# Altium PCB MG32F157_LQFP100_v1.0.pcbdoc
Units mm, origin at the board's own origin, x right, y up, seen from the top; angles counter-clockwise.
Board outline 95.9 x 106.58 mm, 2 copper layers (Top Layer, Bottom Layer); 65 components, 113 nets, 356 pads, 273 vias.
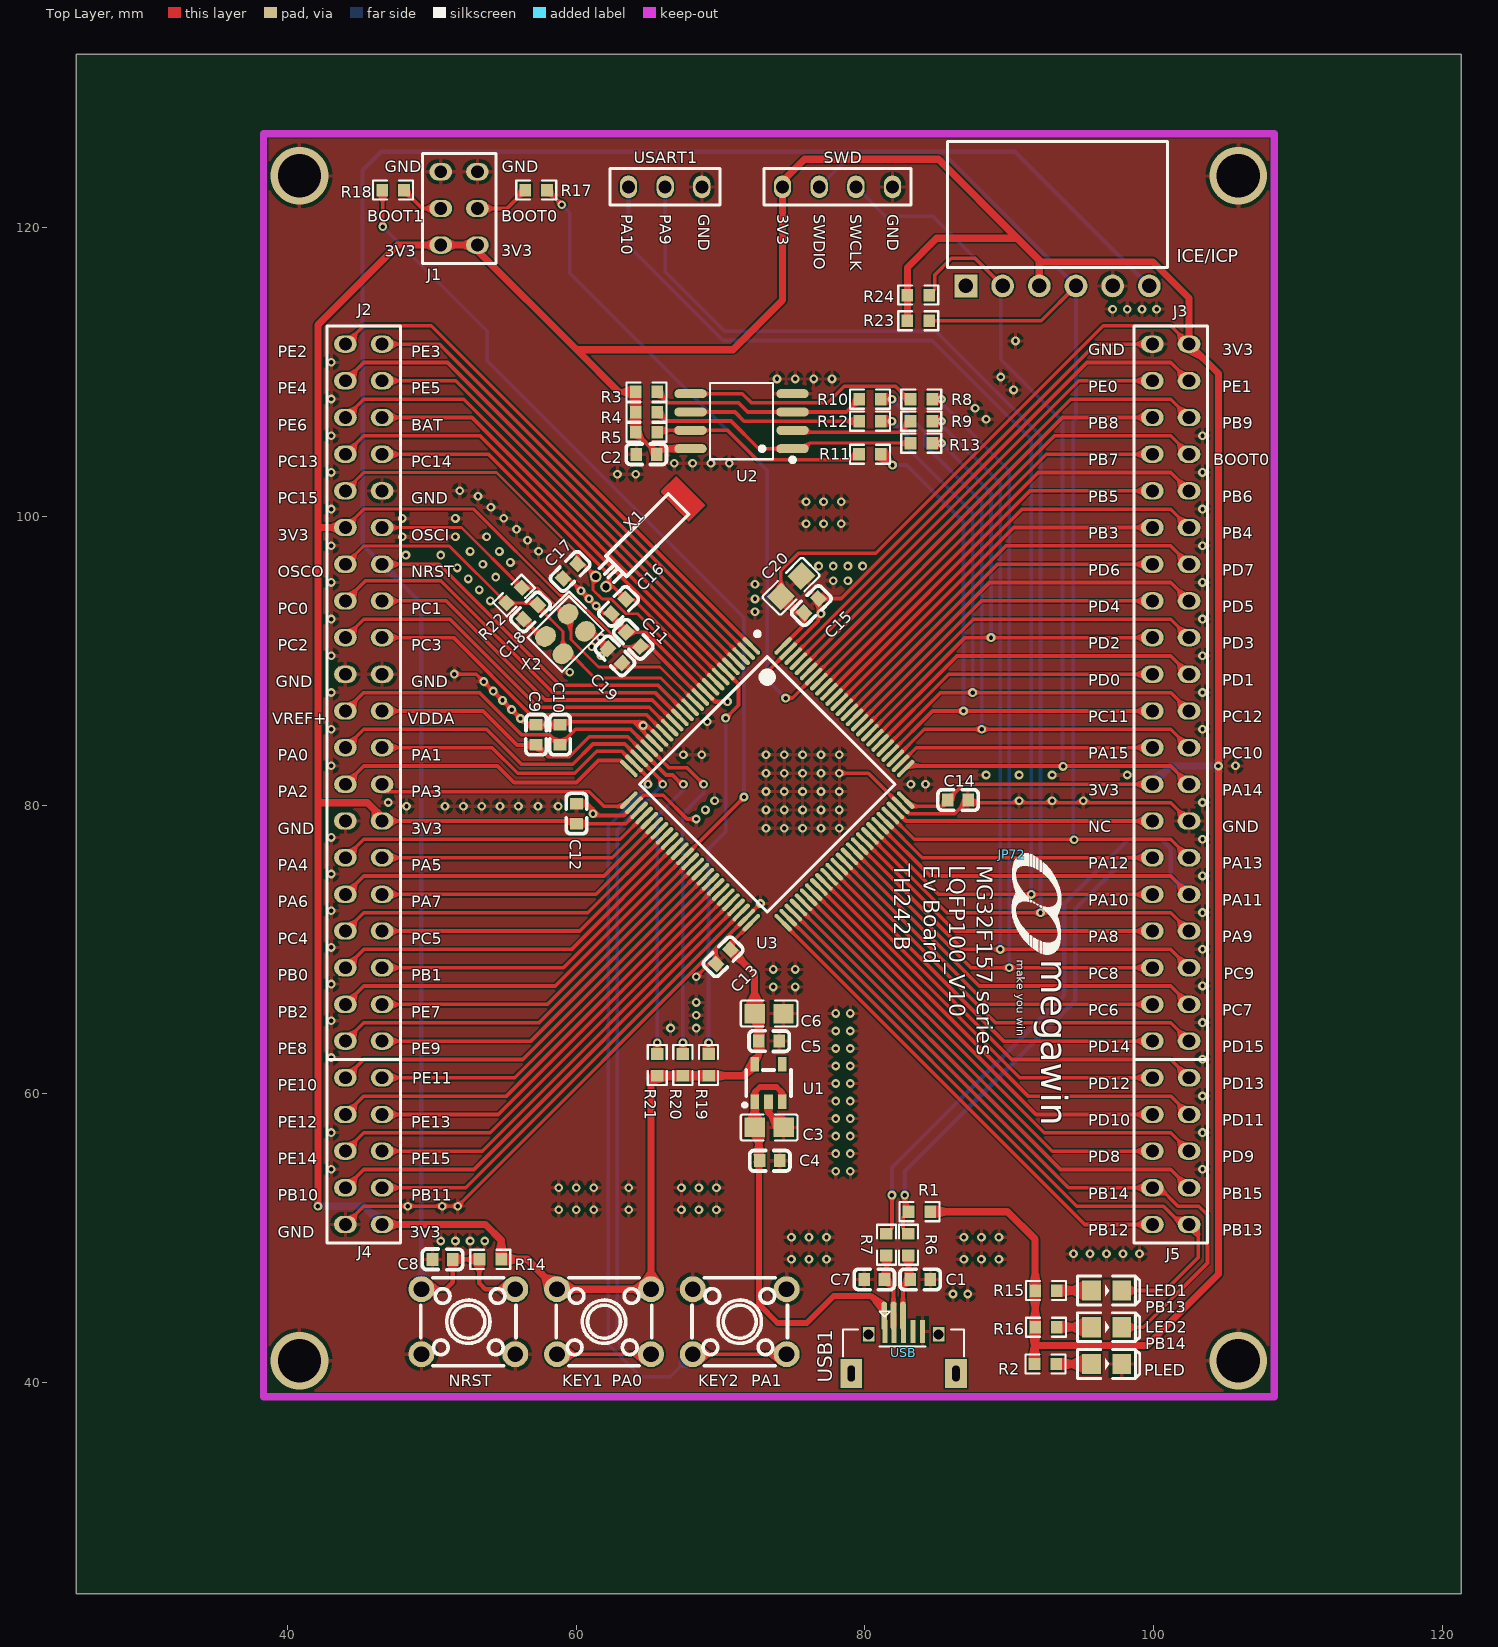
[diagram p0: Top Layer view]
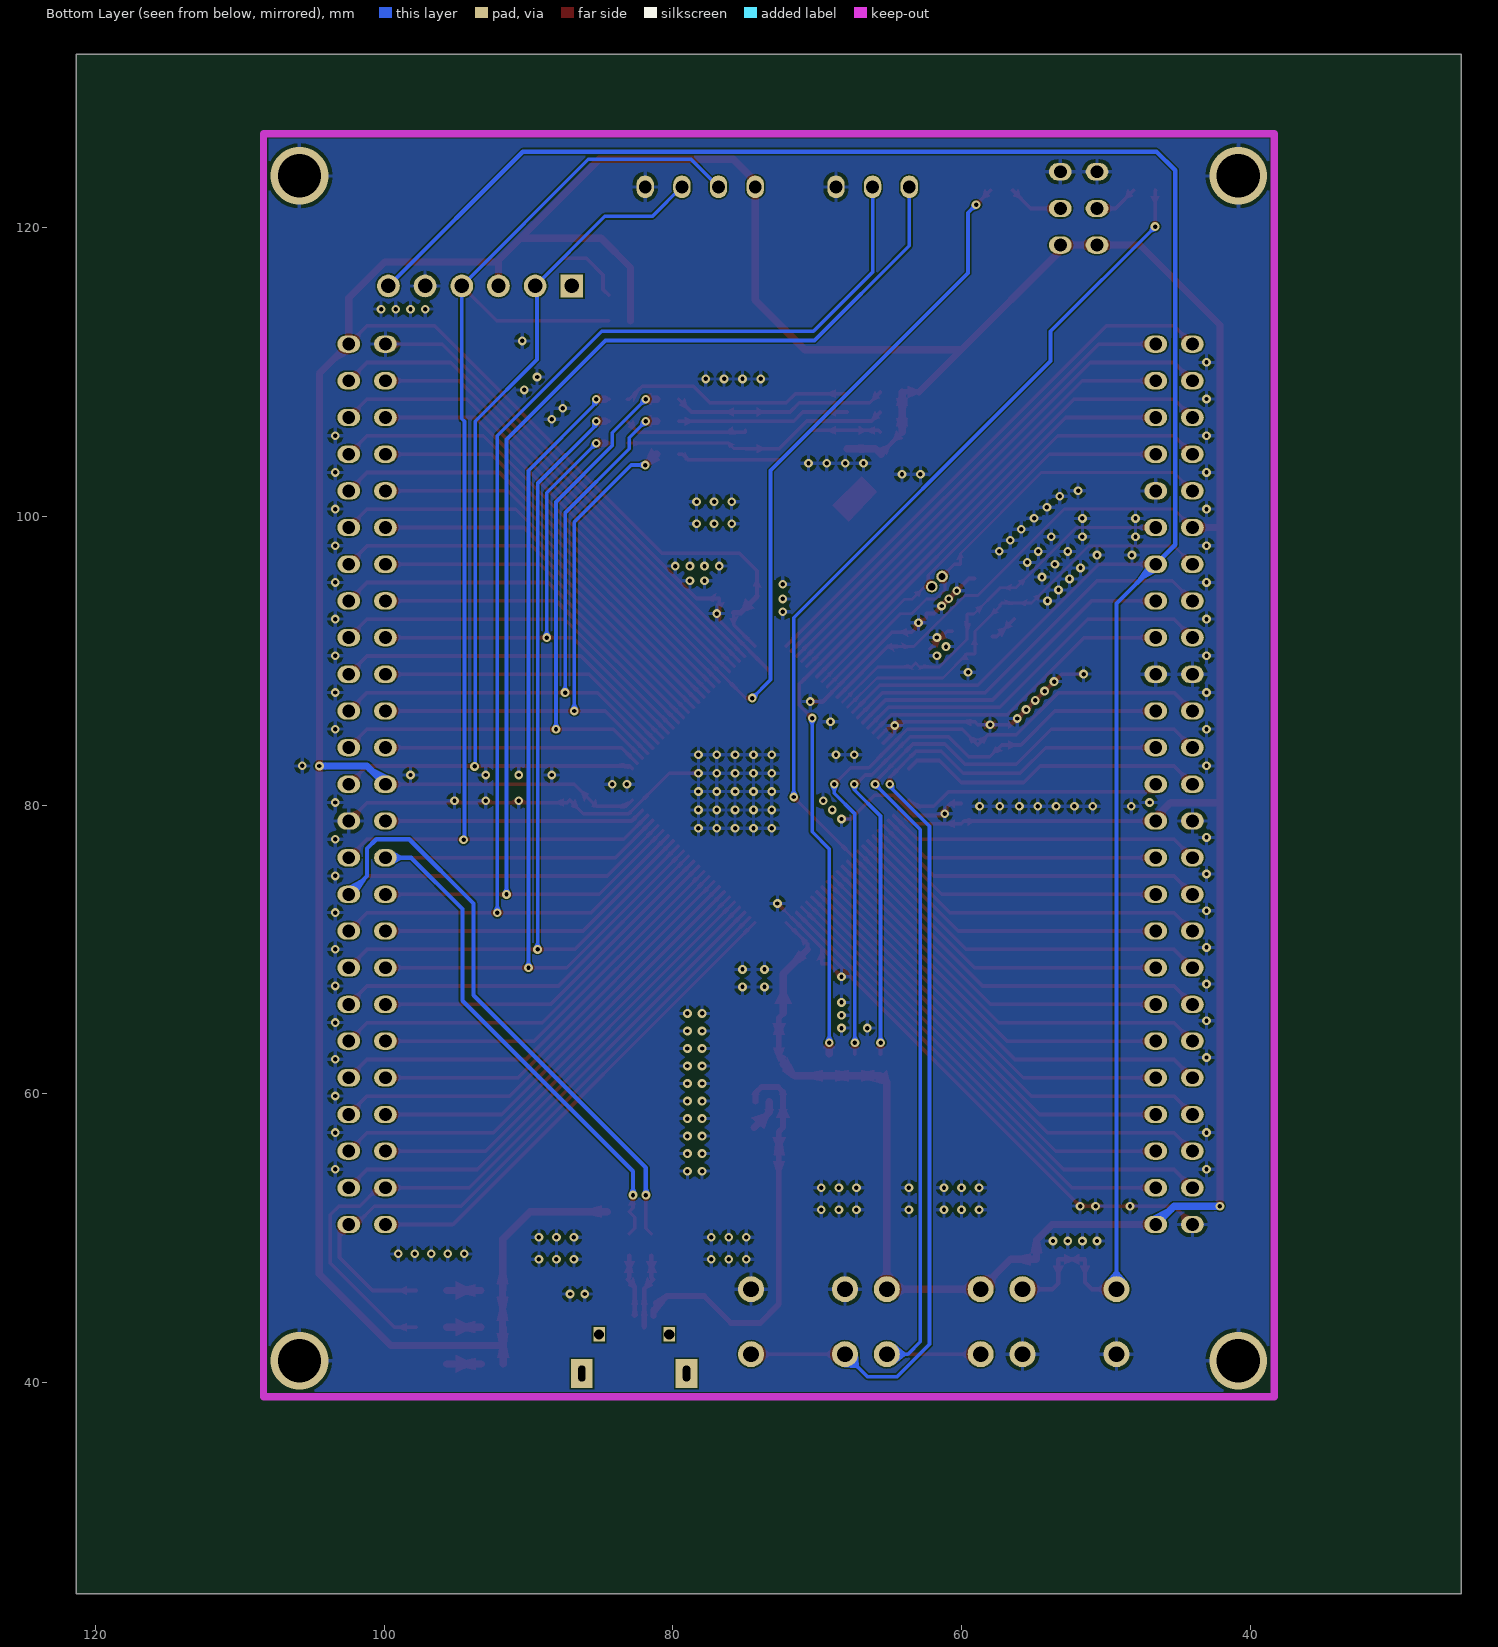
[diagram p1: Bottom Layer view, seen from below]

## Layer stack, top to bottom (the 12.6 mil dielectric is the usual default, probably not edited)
Top Solder: solder mask 0.0102, Solder Resist, Dk 3.5
Top Layer: signal copper 0.0356
Dielectric1: dielectric 0.32, FR-4, Dk 4.8
Bottom Layer: signal copper 0.0356
Bottom Solder: solder mask 0.0102, Solder Resist, Dk 3.5

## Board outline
121.3,25.4 25.4,25.4 25.4,131.979 121.3,131.979

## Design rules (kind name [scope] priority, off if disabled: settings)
Clearance [All] p1: gap=0.1
PolygonConnect [All] p1: connectstyle=Relief reliefconductorwidth=0.254 reliefentries=4 polygonreliefangle="90 Angle" airgapwidth=0.254
RoutingVias [All] p1: holewidth=0.711 width=1.27 viastyle="Through Hole" minholewidth=0.711 minwidth=1.27 maxholewidth=0.711 maxwidth=1.27
SolderMaskExpansion [All] p1: expansion=0.102
Width [All] p1: maxlimit=0.6 minlimit=0.254 preferedwidth=0.254
30 further rules are at their usual default settings.

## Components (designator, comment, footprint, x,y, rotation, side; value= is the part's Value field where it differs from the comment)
C1 "100pF" C0603 83.832,47.152 r0 top
C2 "0.1u" C0603 64.875,104.289 r0 top
C3 "10u" C0805 73.367,57.675 r180 top
C4 "0.1u" C0603 73.406,55.372 r180 top
C5 "0.1u" C0603 73.362,63.657 r180 top
C6 "10u" C0805 73.362,65.562 r180 top
C7 "100pF" C0603 80.657,47.152 r0 top
C8 "0.1u" C0603 50.756,48.544 r0 top
C9 "0.1u" C0603 57.232,84.866 r270 top
C10 "0.1u" C0603 58.883,84.866 r270 top
C11 "0.1u" C0603 63.963,91.47 r315 top
C12 "0.1u" C0603 60.028,79.405 r270 top
C13 "0.1u" C0603 70.188,69.499 r45 top
C14 "0.1u" C0603 86.442,80.35 r180 top
C15 "0.1u" C0603 76.282,93.812 r225 top
C16 "22p" C0603 62.947,93.756 r45 top
C17 "22p" C0603 59.594,96.187 r45 top
C18 "10p" C0603 56.851,93.375 r45 top
C19 "10p" C0603 62.693,90.327 r315 top
C20 "10uF" C0805 74.885,95.153 r225 top
ICE/ICP "*" PS6P254F_90 86.995,115.951 r0 top (schematic designator J8)
J1 "HDR-M-2.54_2x3" HDR-M-2.54_2X3 53.169,118.775 r90 top
J2 "HDR-M-2.54_2x20" HDR-M-2.54_2X20 45.295,87.787 r270 top
J3 "HDR-M-2.54_2x20" HDR-M-2.54_2X20 101.174,87.787 r270 top
J4 "HDR-M-2.54_2x5" HDR-M-2.54_2X5 45.294,56.037 r270 top
J5 "HDR-M-2.54_2x5" HDR-M-2.54_2X5 101.175,56.037 r270 top
JP72 "Comment" MEGAWIN_3.4 90.17,76.581 r270 top
KEY1 "K4-6×6_TH" KEY-TH_4P-L6.0-W6.0-P4.50-LS6.5 61.933,44.226 r0 top
KEY2 "K4-6×6_TH" KEY-TH_4P-L6.0-W6.0-P4.50-LS6.5 71.331,44.226 r0 top
LED1 "LED-0805_R" LED0805_RED 96.73,46.385 r0 top
LED2 "LED-0805_G" LED0805_GREEN 96.73,43.845 r0 top
NRST "K4-6×6_TH" KEY-TH_4P-L6.0-W6.0-P4.50-LS6.5 52.535,44.226 r180 top
PLED "LED-0805_R" LED0805_RED 96.73,41.305 r0 top
R1 "1K5" R0603_NEW 83.775,51.846 r0 top
R2 "1.5k" R0603_NEW 92.495,41.297 r0 top
R3 "10k" R0603_NEW 64.875,108.607 r180 top
R4 "10k" R0603_NEW 64.875,107.21 r180 top
R5 "10k" R0603_NEW 64.875,105.813 r180 top
R6 "10R" R0603_NEW 83.013,49.56 r270 top
R7 "10R" R0603_NEW 81.489,49.56 r270 top
R8 "10R" R0603_NEW 83.904,108.107 r180 top
R9 "10R" R0603_NEW 83.904,106.583 r180 top
R10 "10R" R0603_NEW 80.348,108.107 r180 top
R11 "10R" R0603_NEW 80.346,104.297 r180 top
R12 "10R" R0603_NEW 80.348,106.583 r180 top
R13 "10R" R0603_NEW 83.904,105.059 r180 top
R14 "10k" R0603_NEW 54.059,48.544 r0 top
R15 "1.5k" R0603_NEW 92.54,46.385 r180 top
R16 "1.5k" R0603_NEW 92.54,43.845 r180 top
R17 "10k" R0603_NEW 57.234,122.585 r0 top
R18 "10k" R0603_NEW 47.328,122.585 r0 top
R19 "0R" R0603_NEW 69.172,62.006 r90 top
R20 "0R" R0603_NEW 67.394,62.006 r90 top
R21 "0R" R0603_NEW 65.616,62.006 r90 top
R22 "NC" R0603_NEW 55.708,94.518 r225 top
R23 "10R" R0603_NEW 83.693,113.538 r180 top (schematic designator R13)
R24 "10R" R0603_NEW 83.693,115.316 r180 top (schematic designator R13)
SWD "HDR-M-2.54_1x4" HDR-M-2.54_1X4 78.105,122.809 r0 top
U1 "ME6211C33M5G-N" SOT-23-5_L3.0-W1.7-P0.95-LS2.8-BR 73.327,60.753 r270 top
U2 "W25Q32JWSSIQ_C2980995" SOIC-8_L5.3-W5.3-P1.27-LS8.0-BL 71.457,106.583 r90 top
U3 "WB32F157xx" LQFP-100_L14.0-W14.0-P0.50-LS16.0-BL 73.235,81.437 r225 top
USART1 "HDR-M-2.54_1x3" HDR-M-2.54_1X3 66.167,122.809 r180 top
USB "USB-5P" USB-micro_B 82.677,40.64 r0 top
X1 "32.768kHz" OSC-TH_BD2.0-P0.70-D0.3 61.715,95.478 r225 top
X2 "8MHz" CRYSTAL-SMD_4P-L3.2-W2.5-BL 59.265,91.851 r225 top

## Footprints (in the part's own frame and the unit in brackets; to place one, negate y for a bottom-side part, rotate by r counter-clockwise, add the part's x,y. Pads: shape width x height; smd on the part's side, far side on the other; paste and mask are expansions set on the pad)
C0603 [mm]
  rect 0.8x0.9 smd paste+0 mask+0.051: 1(-0.7,0) 2(0.7,0)
  silkscreen extent -1.41,-0.71 1.39,0.72
C0805 [mm]
  rect 1.41x1.35 smd paste-100 mask+0.051: 1(-1,0) 2(1,0)
  silkscreen extent -1.96,-0.9 1.96,0.9
CRYSTAL-SMD_4P-L3.2-W2.5-BL [mm]
  oval 1.5x1.3 smd paste+0 mask+0.051: 1(-1.1,-0.85) 2(1.1,-0.85) 3(1.1,0.85) 4(-1.1,0.85)
  silkscreen extent -2.26,-1.91 2.03,1.68
HDR-M-2.54_1X3 [mil]
  oval 47.24x62 hole 35 paste+0 mask+2: 1(-100,0) 2(0,0) 3(100,0)
  silkscreen extent -150,-50 150,50
HDR-M-2.54_1X4 [mil]
  oval 47.24x62 hole 35 paste+0 mask+2: 1(-150,0) 2(-50,0) 3(50,0) 4(150,0)
  silkscreen extent -200,-50 200,50
HDR-M-2.54_2X3 [mil]
  oval 47.24x62 hole 35 paste+0 mask+2: 1(0,0) 2(0,100) 3(100,0) 4(100,100) 5(200,0) 6(200,100)
  silkscreen extent -50,-50 250,150
HDR-M-2.54_2X5 [mil]
  oval 47.24x62 hole 35 paste+0 mask+2: 1(-200,-50) 2(-200,50) 3(-100,-50) 4(-100,50) 5(0,-50) 6(0,50) 7(100,-50) 8(100,50) 9(200,-50) 10(200,50)
  silkscreen extent -250,-100 250,100
HDR-M-2.54_2X20 [mil]
  oval 47.24x62 hole 35 paste+0 mask+2: 1(-950,-50) 2(-950,50) 3(-850,-50) 4(-850,50) 5(-750,-50) 6(-750,50) 7(-650,-50) 8(-650,50) 9(-550,-50) 10(-550,50) 11(-450,-50) 12(-450,50) 13(-350,-50) 14(-350,50) 15(-250,-50) 16(-250,50) 17(-150,-50) 18(-150,50) 19(-50,-50) 20(-50,50) 21(50,-50) 22(50,50) 23(150,-50) 24(150,50) 25(250,-50) 26(250,50) 27(350,-50) 28(350,50) 29(450,-50) 30(450,50) 31(550,-50) 32(550,50) 33(650,-50) 34(650,50) 35(750,-50) 36(750,50) 37(850,-50) 38(850,50) 39(950,-50) 40(950,50)
  silkscreen extent -1000,-100 1000,100
KEY-TH_4P-L6.0-W6.0-P4.50-LS6.5 [mm]
  round 1.8 hole 1.1 paste+0 mask+0.051: 1(-3.251,-2.25) 2(3.251,-2.25) 3(3.251,2.25) 4(-3.251,2.25)
  silkscreen extent -3.3,-3.05 3.3,3.05
LED0805_GREEN [mm]
  rect 1.3x1.4 smd paste+0 mask+0.051: 1(-1.05,0) 2(1.05,0)
  silkscreen extent -2,-1 2.3,1
LED0805_RED [mm]
  rect 1.3x1.4 smd paste+0 mask+0.051: 1(-1.05,0) 2(1.05,0)
  silkscreen extent -2,-1 2.3,1
LQFP-100_L14.0-W14.0-P0.50-LS16.0-BL [mm]
  oval 0.3x1.6 smd paste-100 mask+0.051: 1(-6,-7.55) 2(-5.5,-7.55) 3(-5,-7.55) 4(-4.5,-7.55) 5(-4,-7.55) 6(-3.5,-7.55) 7(-3,-7.55) 8(-2.5,-7.55) 9(-2,-7.55) 10(-1.5,-7.55) 11(-1,-7.55) 12(-0.5,-7.55) 13(0,-7.55) 14(0.5,-7.55) 15(1,-7.55) 16(1.5,-7.55) 17(2,-7.55) 18(2.5,-7.55) 19(3,-7.55) 20(3.5,-7.55) 21(4,-7.55) 22(4.5,-7.55) 23(5,-7.55) 24(5.5,-7.55) 25(6,-7.55) 51(6,7.55) 52(5.5,7.55) 53(5,7.55) 54(4.5,7.55) 55(4,7.55) 56(3.5,7.55) 57(3,7.55) 58(2.5,7.55) 59(2,7.55) 60(1.5,7.55) 61(1,7.55) 62(0.5,7.55) 63(0,7.55) 64(-0.5,7.55) 65(-1,7.55) 66(-1.5,7.55) 67(-2,7.55) 68(-2.5,7.55) 69(-3,7.55) 70(-3.5,7.55) 71(-4,7.55) 72(-4.5,7.55) 73(-5,7.55) 74(-5.5,7.55) 75(-6,7.55)
  oval 1.6x0.3 smd paste-100 mask+0.051: 26(7.55,-6) 27(7.55,-5.5) 28(7.55,-5) 29(7.55,-4.5) 30(7.55,-4) 31(7.55,-3.5) 32(7.55,-3) 33(7.55,-2.5) 34(7.55,-2) 35(7.55,-1.5) 36(7.55,-1) 37(7.55,-0.5) 38(7.55,0) 39(7.55,0.5) 40(7.55,1) 41(7.55,1.5) 42(7.55,2) 43(7.55,2.5) 44(7.55,3) 45(7.55,3.5) 46(7.55,4) 47(7.55,4.5) 48(7.55,5) 49(7.55,5.5) 50(7.55,6) 76(-7.55,6) 77(-7.55,5.5) 78(-7.55,5) 79(-7.55,4.5) 80(-7.55,4) 81(-7.55,3.5) 82(-7.55,3) 83(-7.55,2.5) 84(-7.55,2) 85(-7.55,1.5) 86(-7.55,1) 87(-7.55,0.5) 88(-7.55,0) 89(-7.55,-0.5) 90(-7.55,-1) 91(-7.55,-1.5) 92(-7.55,-2) 93(-7.55,-2.5) 94(-7.55,-3) 95(-7.55,-3.5) 96(-7.55,-4) 97(-7.55,-4.5) 98(-7.55,-5) 99(-7.55,-5.5) 100(-7.55,-6)
  silkscreen extent -7.03,-8 6.25,6.25
MEGAWIN_3.4 [mm]
  silkscreen extent -0.05,0.01 6.92,3.44
OSC-TH_BD2.0-P0.70-D0.3 [mm]
  round 0.8 hole 0.5 paste+0 mask+0.051: 1(0,0.5) 2(0,-0.5)
  silkscreen extent -7.6,-1 -0.54,1
PS6P254F_90 [mil]
  rect 62x62 hole 39.37: 1(0,0)
  round 62 hole 39.37: 2(100,0) 3(200,0) 4(300,0) 5(400,0) 6(500,0)
  silkscreen extent -50,50 550,394
R0603_NEW [mm]
  rect 0.806x0.864 smd paste-100 mask+0.051: 1(-0.753,0) 2(0.753,0)
  silkscreen extent -1.39,-0.66 1.39,0.66
SOIC-8_L5.3-W5.3-P1.27-LS8.0-BL [mm]
  oval 0.63x2.25 smd paste+0 mask+0.051: 1(-1.905,-3.53) 2(-0.635,-3.53) 3(0.635,-3.53) 4(1.905,-3.53) 5(1.905,3.53) 6(0.635,3.53) 7(-0.635,3.53) 8(-1.905,3.53)
  silkscreen extent -2.82,-3.68 2.64,2.18
SOT-23-5_L3.0-W1.7-P0.95-LS2.8-BR [mm]
  rect 1x0.6 smd paste+0 mask+0.051: 1(1.3,-0.95) 2(1.3,0) 3(1.3,0.95) 4(-1.3,0.95) 5(-1.3,-0.95)
  silkscreen extent -0.9,-1.78 1.65,1.55
USB-micro_B [mm] "micro型USB ，5.7*7.8*2.5mm"
  rect 0.35x1.6 smd: 1(-1.3,2.9) 2(-0.65,2.9) 3(0,2.9) 4(0.65,2.9) 5(1.3,2.9)
  rect 1.5x2 hole 0.5 slot 1.1 at 90 deg: 5(-3.625,0) 5(3.625,0)
  rect 0.8x1 hole 0.7: 5(-2.425,2.71) 5(2.425,2.71)
  silkscreen extent -4.19,1.17 4.19,4.3, body extent -4,-2.71 4,2.89, height 2.8

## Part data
ICE/ICP: library part CON6
USB: "微型USB母座"

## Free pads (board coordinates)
  oval 0.4x2 smd paste+0 mask+0.051: 1(81.333,44.617) 1(81.983,44.617) 1(82.633,44.617)

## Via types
v1: diameter 0.61, hole 0.305, Top Layer to Bottom Layer, tented both sides, 269 vias
v2: diameter 4, hole 3, Top Layer to Bottom Layer, tented both sides, 4 vias

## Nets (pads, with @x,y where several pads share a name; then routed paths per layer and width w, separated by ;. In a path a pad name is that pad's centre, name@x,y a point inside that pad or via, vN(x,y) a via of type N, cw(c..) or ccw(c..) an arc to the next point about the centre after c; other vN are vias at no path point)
+3V3: C2.2 C5.2 C6.2 C11.2 C12.2 C13.2 C14.2 C15.2 C20.2 ICE/ICP.3 J1.1 J1.2 J2.11 J2.28 J3.2 J3.25 J4.10 KEY1.3 KEY1.4 R1.2 R2.1 R3.2 R4.2 R5.2 R14.2 R15.2 R16.2 R19.1 R20.1 R21.1 R23.2 R24.2 SWD.1 U1.5 U2.8 U3.11 U3.28 U3.50 U3.75 U3.100 | length 454.1
  Top Layer w0.203: J2.11@44.024,99.217 45.294,100.487 52.914,100.487 58.883,94.518 59.772,94.518 63.315,90.975 C11.2
  Top Layer w0.254: J4.10 51.265,50.957 ; J2.28@46.565,78.9 59.832,78.9 C12.2 63.432,78.705 U3.28 ; 60.056,111.506 60.086,111.536 ; C11.2 65.111,90.975 U3.11 ; C13.2 70.682,70.399 U3.50 ; C20.2@74.179,94.447 74.179,96.225 75.393,97.439 80.757,97.439 96.505,113.187 101.174,113.187 J3.2 ; U3.100 75.788,92.475 C15.2@75.788,93.318 ; U3.75 83.244,79.913 85.305,79.913 86.829,81.437 J3.25@99.905,81.437
  Top Layer w0.3: R5.2@64.12,105.813 65.576,104.338 C2.2
  Top Layer w0.381: 62.954,108.607 R3.2 ; C20.2 75.307,93.317 C15.2
  Top Layer w0.4: C6.2 72.662,65.262 C5.2 ; U1.5@72.378,62.054 72.378,62.387 72.662,62.674 C5.2
  Top Layer w0.5: v1@42.119,52.227 42.119,99.217 ; 42.119,80.167 45.549,80.167 46.565,79.151 J2.28 ; J2.11@44.024,99.217 42.119,99.217 ; J4.10 53.727,50.957 54.814,49.872 R14.2 56.613,48.544 KEY1.4 KEY1.3 ; J1.2@50.247,118.775 47.651,118.775 42.119,113.236 42.119,99.217 ; J1.2 J1.1 53.169,118.393 60.056,111.506 62.954,108.607 ; 60.086,111.536 70.866,111.536 74.295,114.965 SWD.1 74.295,123.19 75.819,124.714 85.09,124.714 90.551,119.253 ; R5.2 R3.2 ; KEY1.3 65.184,60.82 R21.1 71.576,61.253 U1.5 ; C2.2 65.963,104.678 U2.8 ; C13.2 72.362,68.315 C6.2 ; R23.2 82.94,115.951 82.94,117.23 84.963,119.253 90.551,119.253 ; R1.2 89.871,51.846 91.786,49.931 R15.2@91.786,46.385 ; R2.1 91.741,43.799 R16.2 R15.2 ; R16.2@91.786,43.845 91.786,42.585 99.533,42.585 104.478,47.528 v1(104.477,82.707) ; ICE/ICP.3 92.075,117.729 90.551,119.253 ; 92.075,117.602 99.949,117.602 102.444,115.107 J3.2 104.477,109.884 v1(104.477,82.707)
  Bottom Layer w0.5: v1(42.12,52.227) 45.294,52.227 J4.10 ; J3.25 101.174,82.707 v1(104.477,82.707)
+5V: C3.2 C4.2 pad.1@81.333,44.617 U1.1 U1.3 USB.1 | length 28.5
  Top Layer w0.4: C3.2 72.662,57.379 C4.2@72.662,55.783 ; C3.2 U1.1 ; U1.1 72.377,60.132 72.727,60.482 73.87,60.482 74.277,60.075 U1.3 ; C4.2@72.662,55.783 72.662,45.433 73.955,44.142 75.974,44.142 77.846,46.014 80.386,46.014 81.334,45.069 pad.1@81.334,44.617
BOOT0: J3.8 R17.2 U3.94 | length 78
  Top Layer w0.254: R17.2 v1(59.004,121.569) v1@59.011,121.569 ; v1(74.505,87.406) 74.961,87.406 93.122,105.567 101.175,105.567 J3.8@102.445,104.297
  Bottom Layer w0.254: v1(59.004,121.569) 59.563,121.01 59.563,116.84 73.235,103.168 73.235,88.676 v1(74.505,87.406)
DN: C7.2 pad.1@81.983,44.617 R7.2 USB.2 | length 5.2
  Top Layer w0.3: R7.2 81.489,47.284 C7.2 81.983,46.525 pad.1@81.983,44.617
  Top Layer w0.4: pad.1@81.983,43.902 pad.1@81.983,44.617
DP: C1.1 pad.1@82.633,44.617 R6.2 USB.3 | length 4.4
  Top Layer w0.3: pad.1@82.633,44.617 82.633,46.653 C1.1 83.013,47.272 R6.2
F1_CLK: R12.2 U2.6 | length 11.9
  Top Layer w0.254: U2.6 70.999,107.218 71.634,106.583 R12.2@79.594,106.583
F1_CS: R4.1 R13.2 U2.1 | length 18.7
  Top Layer w0.203: U2.1 75.774,104.678 76.155,105.059 R13.2@83.15,105.059
  Top Layer w0.254: R4.1 66.246,106.593 70.734,106.593 72.65,104.678 U2.1
F1_DI(IO0): R8.2 U2.5 | length 16.3
  Top Layer w0.254: U2.5 71.507,108.488 72.142,107.853 77.427,107.853 78.57,108.996 82.124,108.996 83.015,108.107 R8.2@83.15,108.107
F1_DO(IO1): R9.2 U2.2 | length 8.6
  Top Layer w0.254: U2.2 74.986,105.821 82.388,105.821 R9.2@83.15,106.583
F1_HOLD(IO3): R5.1 R11.2 U2.7 | length 15
  Top Layer w0.254: R5.1 65.762,105.948 U2.7 70.491,105.948 72.523,103.916 78.949,103.916 79.33,104.297 R11.2@79.591,104.297
F1_WP(IO2): R3.1 R10.2 U2.3 | length 14.9
  Top Layer w0.254: R3.1 66.373,107.863 71.242,107.863 71.888,107.218 U2.3 78.705,107.218 R10.2@79.594,108.107
GND: C1.2 C2.1 C3.1 C4.1 C5.1 C6.1 C7.1 C8.1 C9.1 C10.1 C11.1 C12.1 C13.1 C14.1 C15.1 C16.1 C17.1 C18.1 C19.1 C20.1 ICE/ICP.5 J1.5 J1.6 J2.10 J2.19 J2.20 J2.27 J3.1 J3.28 J4.9 KEY2.3 KEY2.4 NRST.3 NRST.4 PLED.2 SWD.4 U1.2 U2.4 U3.10 U3.19 U3.20 U3.27 U3.49 U3.74 U3.99 USART1.1 USB.5@83.977,43.54 X2.2 X2.4 | length 165.2
  Top Layer w0.203: U3.49 v1(72.758,73.182) v1@72.853,73.182
  Top Layer w0.254: J4.9@44.025,50.957 45.295,52.227 ; v1(48.343,52.227) 45.295,52.227 ; 49.524,52.227 45.295,52.227 ; v1(51.558,89.067) 53.082,89.067 v1(54.902,87.248) ; v1@54.733,87.416 v1(54.902,87.248) ; v1(56.152,85.997) 56.583,85.566 ; C18.1@56.357,92.88 57.563,91.674 X2.2 ; C17.1 C17.1@59.489,95.691 ; C12.1@60.026,80.106 60.775,80.106 61.601,79.278 63.297,79.278 U3.27@64.006,79.987 ; v1(60.339,94.841) C17.1@59.489,95.691 ; X2.4 60.993,92.028 C19.1@62.199,90.822 ; v1(60.894,94.286) C17.1@59.489,95.691 ; 63.957,85.765 U3.20 ; U3.27 64.705,80.685 66.036,80.685 67.687,79.034 v1(68.322,79.034) ; U3.19 64.664,85.765 59.082,85.765 C10.1 56.583,85.566 ; v1(68.322,68.112) 69.214,69.004 C13.1 69.692,70.116 ; U3.10 64.816,91.978 63.455,91.978 62.454,92.981 62.454,93.261 61.919,93.261 C17.1@59.489,95.691 ; U3.49 v1(51.803,52.227) 45.295,52.227 ; 73.275,89.067 73.275,89.256 U3.99 ; U3.99 76.778,92.758 C15.1@76.778,94.308 ; C15.1 78.359,94.307 95.967,111.917 J3.1 ; v1(78.228,82.209) 80.242,82.209 U3.74 83.045,79.405 86.197,79.405 C14.1 87.326,80.167 101.174,80.167 J3.28 ; v1(54.902,87.248) 56.583,85.566
  Top Layer w0.3: U3.10 69.631,87.162 v1(70.481,87.162)
  Top Layer w0.5: U1.2 73.328,58.714 C3.1
  other v1: 86.102,46.141 87.118,46.141 74.912,48.554 76.126,48.554 77.339,48.554 86.85,48.554 88.064,48.554 89.277,48.554 94.443,48.925 95.586,48.925 96.729,48.925 97.872,48.925 99.015,48.925 50.628,49.814 51.644,49.814 52.66,49.814 53.676,49.814 74.912,50.078 76.126,50.078 77.339,50.078 86.85,50.078 88.064,50.078 89.277,50.078 58.797,51.983 60.01,51.983 61.224,51.983 63.651,51.983 67.292,51.983 68.506,51.983 69.719,51.983 50.73,52.227 58.797,53.507 60.01,53.507 61.224,53.507 63.651,53.507 67.292,53.507 68.506,53.507 69.719,53.507 77.974,54.65 78.99,54.65 43.049,54.777 103.374,54.777 77.974,55.864 78.99,55.864 77.974,57.077 78.99,57.077 43.049,57.317 103.374,57.317 77.974,58.291 78.99,58.291 77.974,59.504 78.99,59.504 103.374,59.857 77.974,60.718 78.99,60.718 77.974,61.931 78.99,61.931 103.374,62.397 43.049,62.524 77.974,63.145 78.99,63.145 77.974,64.359 78.99,64.359 66.544,64.556 68.322,64.556 103.374,64.937 43.049,65.064 68.322,65.445 77.974,65.572 78.99,65.572 68.322,66.334 73.656,67.407 75.18,67.407 103.374,67.477 43.049,67.604 73.656,68.62 75.18,68.62 103.374,70.017 43.049,70.144 103.374,72.557 43.049,72.684 103.374,75.097 43.049,75.224 103.374,77.637 43.049,77.764 73.148,78.399 74.418,78.399 75.688,78.399 76.958,78.399 78.228,78.399 61.169,79.405 68.957,79.669 73.148,79.669 74.418,79.669 75.688,79.669 76.958,79.669 78.228,79.669 57.359,79.913 58.756,79.913 48.256,79.923 50.923,79.923 52.193,79.923 53.463,79.923 54.733,79.923 56.003,79.923 46.986,80.177 103.374,80.177 69.592,80.304 90.674,80.304 92.96,80.304 95.119,80.304 73.148,80.939 74.418,80.939 75.688,80.939 76.958,80.939 78.228,80.939 83.181,81.447 84.197,81.447 88.388,82.082 90.674,82.082 92.96,82.082 98.167,82.082 73.148,82.209 74.418,82.209 75.688,82.209 76.958,82.209 43.049,82.717 105.66,82.717 67.433,83.479 68.703,83.479 73.148,83.479 74.418,83.479 75.688,83.479 76.958,83.479 78.228,83.479 43.049,85.257 103.374,85.257 64.639,85.511 58.035,85.566 69.084,85.765 55.537,86.613 43.049,87.797 103.374,87.797 54.26,87.889 53.6,88.549 59.559,89.194 43.049,90.337 61.718,90.337 103.374,90.337 61.083,90.972 61.718,91.607 62.988,92.623 43.049,92.877 103.374,92.877 76.958,93.258 72.386,93.385 61.392,93.788 54.057,94.137 72.386,94.274 53.295,94.899 72.386,95.29 43.049,95.417 103.374,95.417 77.806,95.534 78.822,95.534 52.533,95.661 54.438,95.788 51.771,96.423 76.79,96.55 77.806,96.55 78.822,96.55 79.838,96.55 53.549,96.677 55.454,96.804 48.215,97.312 50.628,97.312 52.66,97.566 54.692,97.566 57.4,97.576 43.049,97.957 103.374,97.957 56.638,98.338 47.961,98.582 51.644,98.582 53.803,98.582 55.876,99.1 75.928,99.481 77.142,99.481 78.355,99.481 47.961,99.852 51.644,99.852 54.987,99.862 43.049,100.497 103.374,100.497 54.098,100.624 75.928,101.005 77.142,101.005 78.355,101.005 53.209,101.386 51.939,101.767 62.861,102.91 64.131,102.91 43.049,103.037 103.374,103.037 66.798,103.672 68.068,103.672 69.338,103.672 70.608,103.672 43.049,105.577 103.374,105.577 88.388,106.72 87.626,107.482 43.049,108.117 90.293,108.752 73.91,109.514 75.18,109.514 76.45,109.514 77.72,109.514 89.404,109.641 43.049,110.657 90.424,112.141 97.151,114.34 98.167,114.34 99.183,114.34 100.199,114.34
  other v2: 40.85,41.529 105.85,41.529 40.85,123.571 105.85,123.571
J1_3: J1.3 R17.1 | length 3.8
  Top Layer w0.254: J1.3@53.168,121.315 55.21,121.315 R17.1@56.48,122.585
J1_4: J1.4 R18.2 | length 3.1
  Top Layer w0.254: R18.2 49.352,121.315 J1.4
NC: J3.27 U3.73 | length 18.1
  Top Layer w0.254: U3.73 82.846,78.897 J3.27@99.905,78.897
NRST: C8.2 ICE/ICP.6 J2.14 NRST.1 NRST.2 R14.1 U3.14 | length 173.4
  Top Layer w0.254: J2.14@46.564,96.677 50.501,96.677 58.883,88.295 65.67,88.295 U3.14@67.542,86.423
  Top Layer w0.3: NRST.2 50.974,46.476 51.456,46.958 C8.2 53.305,48.544 53.305,46.883 53.711,46.476 NRST.1@55.784,46.476
  Bottom Layer w0.3: NRST.2 49.283,93.959 J2.14 45.216,98.026 45.216,112.337 45.212,112.341 45.212,123.952 46.505,125.245 90.401,125.245 ICE/ICP.6
OSC_IN: C19.2 J2.12 R22.1 U3.12 X2.1 | length 27.9
  Top Layer w0.203: J2.12 52.074,99.217 R22.1 57.334,95.051 59.155,93.23 X2.1 ; X2.1 59.645,93.23 59.645,91.47 61.55,89.565 62.921,89.565 C19.2 63.455,89.565 65.814,89.565 U3.12
OSC_OUT: C18.2 J2.13 R22.2 U3.13 X2.3 | length 30
  Top Layer w0.203: J2.13 45.295,97.947 51.213,97.947 R22.2 57.231,93.985 C18.2 57.346,93.769 59.088,92.027 X2.3 59.627,90.472 61.296,88.803 65.868,88.803 U3.13
PA0: J2.23 KEY1.1 KEY1.2 U3.23 | length 74.4
  Top Layer w0.254: J2.23@44.024,83.977 45.294,85.247 53.803,85.247 56.216,82.834 59.772,82.834 61.169,84.231 63.371,84.231 U3.23 ; KEY1.1 KEY1.2 ; U3.23 65.996,81.605 v1(65.996,81.437)
  Bottom Layer w0.254: KEY1.2@65.182,41.976 63.724,41.976 62.86,42.839 62.86,78.303 v1(65.996,81.437)
PA1: J2.24 KEY2.1 KEY2.2 U3.24 | length 74.9
  Top Layer w0.254: J2.24@46.564,83.977 54.184,83.977 55.962,82.199 59.899,82.199 61.423,83.723 63.17,83.723 U3.24@64.006,82.887 ; U3.24 64.98,81.913 v1(64.98,81.437) ; KEY2.1 KEY2.2
  Bottom Layer w0.254: v1@64.979,81.437 64.979,81.28 62.225,78.526 62.225,42.661 64.471,40.416 66.521,40.416 KEY2.1@68.078,41.976
PA2: J2.25 U3.25 | length 21.5
  Top Layer w0.254: J2.25@44.024,81.437 45.294,82.707 54.565,82.707 55.708,81.564 60.026,81.564 61.55,83.088 63.099,83.088 U3.25@63.653,82.532
PA3: J2.26 U3.26 | length 18.2
  Top Layer w0.254: J2.26@46.564,81.437 46.564,80.929 60.915,80.929 61.933,79.913 63.226,79.913 U3.26@63.653,80.34
PA4: J2.29 U3.29 | length 21.9
  Top Layer w0.254: J2.29@44.024,76.357 45.294,77.627 63.061,77.627 U3.29
PA5: J2.30 U3.30 | length 19.6
  Top Layer w0.254: J2.30 62.498,76.357 U3.30
PA6: J2.31 U3.31 | length 23.4
  Top Layer w0.254: J2.31 45.295,75.087 61.935,75.087 U3.31
PA7: J2.32 U3.32 | length 21
  Top Layer w0.254: J2.32 61.372,73.817 U3.32
PA8: J3.33 U3.67 | length 22.5
  Top Layer w0.254: U3.67 86.223,71.277 J3.33@99.905,71.277
PA9: J3.34 U3.68 USART1.2 | length 94.4
  Top Layer w0.254: U3.68 85.661,72.547 101.175,72.547 J3.34@102.445,71.277
  Bottom Layer w0.254: USART1.2 66.167,116.908 70.269,112.806 75.903,112.806 84.92,112.806 92.159,105.567 v1(92.158,72.547)
PA10: J3.31 U3.69 USART1.3 | length 90.1
  Top Layer w0.254: U3.69 85.098,73.817 J3.31@99.905,73.817
  Bottom Layer w0.254: USART1.3 63.627,118.73 70.186,112.171 84.666,112.171 91.522,105.316 v1(91.522,73.817)
PA11: J3.32 R7.1 U3.70 | length 64.5
  Top Layer w0.254: U3.70 84.535,75.087 101.175,75.087 J3.32@102.445,73.817 ; R7.1 81.87,50.694 v1(81.87,52.989)
  Bottom Layer w0.3: v1(81.87,52.989) 81.87,54.894 93.808,66.832 93.808,73.182 98.253,77.627 100.539,77.627 101.174,76.992 101.174,75.087 J3.32
PA12: J3.29 R1.1 R6.1 U3.71 | length 54.2
  Top Layer w0.254: U3.71 83.972,76.357 J3.29@99.905,76.357 ; v1(82.759,52.989) 82.759,52.109 R1.1 ; R6.1@83.013,50.314 82.632,50.695 82.632,51.455 R1.1@83.02,51.846
  Bottom Layer w0.3: v1(82.759,52.989) 82.759,54.64 94.57,66.451 94.57,72.801 98.126,76.357 J3.29
PA13: ICE/ICP.4 J3.30 R23.1 SWD.2 U3.72 | length 93.6
  Top Layer w0.254: U3.72 83.409,77.627 101.175,77.627 J3.30@102.445,76.357 ; R23.1 92.202,113.538 ICE/ICP.4
  Bottom Layer w0.254: SWD.2 78.74,124.714 85.852,124.714 ICE/ICP.4 94.615,106.758 94.433,106.576 v1@94.433,77.652
  other v1: 94.488,77.597
PA14: ICE/ICP.2 J3.26 R24.1 SWD.3 U3.76 | length 75.5
  Top Layer w0.254: U3.76 82.99,82.707 101.175,82.707 J3.26@102.445,81.437 ; R24.1 84.836,115.706 84.836,116.713 85.979,117.856 87.63,117.856 ICE/ICP.2
  Bottom Layer w0.254: SWD.3 81.407,120.777 84.709,120.777 ICE/ICP.2 ; ICE/ICP.2@89.154,115.6 89.408,115.346 89.408,110.856 93.683,106.583 v1@93.683,82.72
  other v1: 93.726,82.677
PA15: J3.23 U3.77 | length 17.9
  Top Layer w0.254: U3.77 83.553,83.977 J3.23@99.905,83.977
PB0: J2.35 U3.35 | length 26.3
  Top Layer w0.254: J2.35 45.295,70.007 59.683,70.007 U3.35
PB1: J2.36 U3.36 | length 24
  Top Layer w0.254: J2.36 59.121,68.737 U3.36
PB2: J2.37 R18.1 U3.37 | length 86
  Top Layer w0.254: J2.37@44.024,66.197 45.294,67.467 58.558,67.467 U3.37@67.542,76.451 ; R18.1 46.605,122.555 v1(46.605,120.055) ; U3.37 71.624,80.533 v1(71.624,80.558)
  Bottom Layer w0.254: v1(46.605,120.055) 53.844,112.816 53.844,110.748 71.624,92.968 v1(71.624,80.558)
PB3: J3.11 U3.89 | length 26.7
  Top Layer w0.254: U3.89 90.308,99.217 J3.11@99.905,99.217
PB4: J3.12 U3.90 | length 30.5
  Top Layer w0.254: U3.90 90.871,100.487 101.175,100.487 J3.12@102.445,99.217
PB5: J3.9 U3.91 | length 28.2
  Top Layer w0.254: U3.91 91.434,101.757 J3.9@99.905,101.757
PB6: J3.10 U3.92 | length 32
  Top Layer w0.254: U3.92@77.158,88.191 91.997,103.027 101.174,103.027 J3.10
PB7: J3.7 U3.93 | length 29.6
  Top Layer w0.254: U3.93 92.559,104.297 J3.7@99.905,104.297
PB8: J3.5 U3.95 | length 31.1
  Top Layer w0.254: U3.95 93.685,106.837 J3.5@99.905,106.837
PB9: J3.6 U3.96 | length 34.9
  Top Layer w0.254: U3.96 94.248,108.107 101.175,108.107 J3.6@102.445,106.837
PB10: J4.7 U3.47 | length 35.1
  Top Layer w0.254: J4.7@44.025,53.497 45.295,54.767 52.929,54.767 U3.47
PB11: J4.8 U3.48 | length 32.8
  Top Layer w0.254: J4.8@46.565,53.497 52.366,53.497 U3.48
PB12: J5.9 U3.51 | length 34.2
  Top Layer w0.254: U3.51 95.23,50.957 J5.9
PB13: J5.10 LED1.2 U3.52 | length 45.7
  Top Layer w0.254: U3.52 94.666,52.227 100.668,52.227 101.936,50.957 102.444,50.957 103.081,50.957 103.081,48.671 100.795,46.385 LED1.2
PB14: J5.7 LED2.2 U3.53 | length 48.5
  Top Layer w0.254: U3.53 94.104,53.497 J5.7 ; LED2.2 99.269,43.845 103.716,48.29 103.716,51.635 103.124,52.227 101.682,52.227 100.412,53.497 J5.7@99.904,53.497
PB15: J5.8 U3.54 | length 35.1
  Top Layer w0.254: U3.54 93.541,54.767 101.175,54.767 J5.8
PC0: J2.15 U3.15 | length 27.7
  Top Layer w0.254: J2.15@44.024,94.137 45.421,95.534 50.628,95.534 58.375,87.787 65.471,87.787 U3.15
PC1: J2.16 U3.16 | length 23.8
  Top Layer w0.254: J2.16@46.564,94.137 51.009,94.137 57.867,87.279 65.271,87.279 U3.16
PC2: J2.17 U3.17 | length 26.1
  Top Layer w0.254: J2.17@44.024,91.597 45.294,92.867 51.263,92.867 57.359,86.771 65.073,86.771 U3.17
PC3: J2.18 U3.18 | length 22.3
  Top Layer w0.254: J2.18@46.564,91.597 51.517,91.597 56.851,86.263 64.872,86.263 U3.18
PC4: J2.33 U3.33 | length 24.8
  Top Layer w0.254: J2.33 45.295,72.547 60.809,72.547 U3.33
PC5: J2.34 U3.34 | length 22.5
  Top Layer w0.254: J2.34 60.246,71.277 U3.34
PC6: J3.37 U3.63 | length 25.4
  Top Layer w0.254: U3.63 88.475,66.197 J3.37@99.905,66.197
PC7: J3.38 U3.64 | length 27.8
  Top Layer w0.254: U3.64 87.912,67.467 101.175,67.467 J3.38@102.445,66.197
PC8: J3.35 R8.1 U3.65 | length 66.8
  Top Layer w0.254: U3.65 87.349,68.737 J3.35@99.905,68.737 ; R8.1@84.402,108.107 v1(85.3,108.107)
  Top Layer w0.5: R8.1 v1(85.3,108.107)
  Bottom Layer w0.254: v1(85.3,108.107) 85.301,107.85 90,103.154 v1(89.999,68.737)
PC9: J3.36 R9.1 U3.66 | length 66.1
  Top Layer w0.254: U3.66 86.786,70.007 101.175,70.007 J3.36@102.445,68.737 ; R9.1@84.402,106.583 v1(85.3,106.583)
  Top Layer w0.5: R9.1 v1(85.3,106.583)
  Bottom Layer w0.254: v1(85.3,106.583) 85.301,106.326 89.365,102.262 v1(89.364,70.007)
PC10: J3.24 R10.1 U3.78 | length 48.7
  Top Layer w0.254: R10.1@81.1,108.107 v1(81.871,108.107) ; U3.78 84.116,85.247 101.175,85.247 J3.24@102.445,83.977
  Top Layer w0.5: R10.1 v1(81.871,108.107)
  Bottom Layer w0.254: v1(81.871,108.107) 84.196,105.78 84.196,104.891 88.095,100.992 v1(88.094,85.247)
PC11: J3.21 R11.1 U3.79 | length 41.2
  Top Layer w0.254: R11.1 81.159,104.297 v1(81.911,103.545) ; U3.79 84.679,86.517 J3.21@99.905,86.517
  Top Layer w0.5: R11.1 81.159,104.297 v1(81.911,103.545)
  Bottom Layer w0.254: v1(81.911,103.545) 82.876,103.545 86.825,99.595 v1(86.824,86.517)
PC12: J3.22 R12.1 U3.80 | length 45.8
  Top Layer w0.254: R12.1@81.1,106.583 v1(81.871,106.583) ; U3.80 85.242,87.787 101.175,87.787 J3.22@102.445,86.517
  Top Layer w0.5: R12.1 v1(81.871,106.583)
  Bottom Layer w0.254: v1(81.871,106.583) 83.02,105.435 83.02,104.67 87.46,100.23 v1(87.459,87.787)
PC13: J2.7 U3.7 | length 33.4
  Top Layer w0.254: J2.7 45.295,105.567 53.348,105.567 U3.7
PC14: C16.2 J2.8 U3.8 X1.1 | length 30.6
  Top Layer w0.203: X1.1 62.568,95.125 C16.2 63.957,94.251 U3.8
  Top Layer w0.254: J2.8@46.564,104.297 53.93,104.297 62.312,95.915 62.312,95.125 X1.1
PC15: C17.2 J2.9 U3.9 X1.2 | length 33.3
  Top Layer w0.203: J2.9 45.295,103.027 54.489,103.027 60.089,97.426 C17.2 ; X1.2@61.362,95.834 61.169,95.834 61.169,94.899 61.804,94.264 62.439,94.264 63.455,93.248 64.252,93.248 U3.9@69.309,88.191
  Top Layer w0.254: C17.2@60.089,96.681 60.513,96.681 X1.2
PD0: J3.19 U3.81 | length 20.8
  Top Layer w0.254: U3.81 85.805,89.057 J3.19@99.905,89.057
PD1: J3.20 U3.82 | length 24.6
  Top Layer w0.254: U3.82 86.368,90.327 101.175,90.327 J3.20@102.445,89.057
PD2: J3.17 R13.1 U3.83 | length 38.7
  Top Layer w0.254: U3.83 86.931,91.597 J3.17@99.905,91.597 ; R13.1@84.402,105.059 v1(85.3,105.059)
  Top Layer w0.5: R13.1 v1(85.3,105.059)
  Bottom Layer w0.254: v1(85.3,105.059) 88.73,101.63 v1(88.729,91.597)
PD3: J3.18 U3.84 | length 26.1
  Top Layer w0.254: U3.84 87.493,92.867 101.174,92.867 J3.18
PD4: J3.15 U3.85 | length 23.8
  Top Layer w0.254: U3.85 88.056,94.137 J3.15@99.905,94.137
PD5: J3.16 U3.86 | length 27.6
  Top Layer w0.254: U3.86 88.619,95.407 101.175,95.407 J3.16@102.445,94.137
PD6: J3.13 U3.87 | length 25.2
  Top Layer w0.254: U3.87 89.182,96.677 J3.13@99.905,96.677
PD7: J3.14 U3.88 | length 29
  Top Layer w0.254: U3.88 89.745,97.947 101.175,97.947 J3.14@102.445,96.677
PD8: J5.5 U3.55 | length 31.3
  Top Layer w0.254: U3.55 92.978,56.037 J5.5
PD9: J5.6 U3.56 | length 33.6
  Top Layer w0.254: U3.56 92.415,57.307 101.175,57.307 J5.6
PD10: J5.3 U3.57 | length 29.8
  Top Layer w0.254: U3.57 91.852,58.577 J5.3
PD11: J5.4 U3.58 | length 32.2
  Top Layer w0.254: U3.58 91.289,59.847 101.175,59.847 J5.4
PD12: J5.1 U3.59 | length 28.4
  Top Layer w0.254: U3.59 90.726,61.117 J5.1
PD13: J5.2 U3.60 | length 30.7
  Top Layer w0.254: U3.60 90.164,62.387 101.175,62.387 J5.2
PD14: J3.39 U3.61 | length 26.9
  Top Layer w0.254: U3.61 89.601,63.657 J3.39@99.905,63.657
PD15: J3.40 U3.62 | length 29.2
  Top Layer w0.254: U3.62 89.038,64.927 101.175,64.927 J3.40@102.445,63.657
PE0: J3.3 U3.97 | length 32.6
  Top Layer w0.254: U3.97 94.811,109.377 J3.3@99.905,109.377
PE1: J3.4 U3.98 | length 36.4
  Top Layer w0.254: U3.98@75.037,90.312 95.375,110.647 101.174,110.647 J3.4
PE2: J2.1 U3.1 | length 37.8
  Top Layer w0.254: J2.1 45.295,113.187 49.97,113.187 U3.1
PE3: J2.2 U3.2 | length 34
  Top Layer w0.254: J2.2 50.533,111.917 U3.2
PE4: J2.3 U3.3 | length 36.4
  Top Layer w0.254: J2.3 45.295,110.647 51.096,110.647 U3.3
PE5: J2.4 U3.4 | length 32.6
  Top Layer w0.254: J2.4 51.659,109.377 U3.4
PE6: J2.5 U3.5 | length 34.9
  Top Layer w0.254: J2.5 45.295,108.107 52.222,108.107 U3.5
PE7: J2.38 U3.38 | length 25.4
  Top Layer w0.254: J2.38 57.995,66.197 U3.38
PE8: J2.39 U3.39 | length 29.2
  Top Layer w0.254: J2.39@44.024,63.657 45.294,64.927 57.432,64.927 U3.39
PE9: J2.40 U3.40 | length 26.9
  Top Layer w0.254: J2.40 56.869,63.657 U3.40
PE10: J4.1 U3.41 | length 30.7
  Top Layer w0.254: J4.1 45.294,62.387 56.307,62.387 U3.41@68.956,75.039
PE11: J4.2 U3.42 | length 28.4
  Top Layer w0.254: J4.2@46.565,61.117 55.743,61.117 U3.42
PE12: J4.3 U3.43 | length 32.2
  Top Layer w0.254: J4.3@44.025,58.577 45.295,59.847 55.181,59.847 U3.43
PE13: J4.4 U3.44 | length 29.8
  Top Layer w0.254: J4.4@46.565,58.577 54.618,58.577 U3.44
PE14: J4.5 U3.45 | length 33.6
  Top Layer w0.254: J4.5@44.025,56.037 45.295,57.307 54.055,57.307 U3.45
PE15: J4.6 U3.46 | length 31.3
  Top Layer w0.254: J4.6 53.493,56.037 U3.46@70.724,73.271
R2_2: PLED.1 R2.2 | length 2.4
  Top Layer w0.5: R2.2 PLED.1
R15_1: LED1.1 R15.1 | length 2.4
  Top Layer w0.5: R15.1 LED1.1
R16_1: LED2.1 R16.1 | length 2.4
  Top Layer w0.5: R16.1 LED2.1
S$68132: 
S$68136: 
S$68140: 
U1_4: U1.4
USB1_4: USB.4
USB1_6: 
USB1_7: 
USB1_8: 
USB1_9: 
VBAT: J2.6 R19.2 U3.6 | length 59.6
  Top Layer w0.254: J2.6 52.785,106.837 U3.6 71.243,88.379 71.243,86.908 v1(70.354,86.019) ; R19.2 v1(69.172,63.54)
  Top Layer w0.5: R19.2 v1(69.172,63.54)
  Bottom Layer w0.254: v1(69.172,63.54) 69.172,76.964 70.353,78.145 v1(70.354,86.019)
VDDA: C9.2 J2.22 R21.2 U3.22 | length 43.6
  Top Layer w0.254: J2.22@46.564,86.517 53.549,86.517 55.901,84.165 C9.2 58.057,83.342 59.518,83.342 60.915,84.739 63.569,84.739 U3.22 66.226,82.082 66.671,82.082 67.306,81.447 v1(67.433,81.447) ; R21.2 v1(65.616,63.54)
  Bottom Layer w0.254: v1(65.616,63.54) 65.616,79.249 67.433,81.066 v1(67.433,81.447)
VREF+: C10.2 J2.21 R20.2 U3.21 | length 48.1
  Top Layer w0.254: J2.21@44.024,86.517 45.294,87.787 53.295,87.787 56.216,84.866 58.184,84.866 C10.2 59.965,85.247 63.767,85.247 U3.21 66.425,82.59 67.687,82.59 v1(68.83,81.447) ; R20.2 v1(67.394,63.54)
  Bottom Layer w0.254: v1(67.394,63.54) 67.394,79.376 68.83,80.812 v1(68.83,81.447)
pads on no net: ICE/ICP.1 USB.5@79.052,40.64 USB.5@80.252,43.35 USB.5@85.102,43.35 USB.5@86.302,40.64

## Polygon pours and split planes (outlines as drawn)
GND on Bottom Layer "Top Layer-No Net" (solid, remove dead copper, pour order 6): 38.35,126.492 108.35,126.492 108.35,39.029 38.35,39.029
GND on Top Layer "Top Layer-No Net" (solid, remove dead copper, pour order 8): 38.35,126.492 108.35,126.492 108.35,39.135 108.204,38.989 108.164,39.029 38.35,39.029

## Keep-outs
Keep-Out Layer:
  lines w0.5: 38.35,39.029 38.35,126.492 108.35,126.492 108.35,39.029 38.35,39.029

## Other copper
Top Layer:
  drawing of 474 lines, arcs and shapes, not listed
Bottom Layer:
  region net PC8: 89.77,68.938 90.228,68.938 90.126,69.152 89.872,69.152
  region net PC8: 85.151,107.841 85.583,107.992 85.57,107.761 85.304,107.668
  region net PC11: 86.595,86.718 87.053,86.718 86.951,86.932 86.697,86.932
  region net PC11: 82.113,103.316 82.113,103.774 82.326,103.672 82.326,103.418
  region net PC12: 87.23,87.988 87.688,87.988 87.586,88.202 87.332,88.202
  region net PC12: 82.175,106.602 81.852,106.278 82.075,106.199 82.255,106.379
  region net PC10: 88.323,85.448 87.866,85.449 87.968,85.662 88.222,85.662
  region net PC10: 82.175,108.126 81.853,107.802 82.076,107.724 82.255,107.904
  region net PC9: 89.593,70.208 89.136,70.209 89.238,70.422 89.492,70.422
  region net PC9: 85.151,106.317 85.583,106.468 85.57,106.237 85.304,106.144
  region net PD2: 88.958,91.798 88.501,91.799 88.603,92.012 88.857,92.012
  region net PD2: 85.604,105.079 85.282,104.754 85.505,104.676 85.684,104.856
  region net NRST: 47.283,96.396 46.604,96.077 47.357,95.673 47.757,95.697
  region net +3V3: 46.376,51.557 46.751,51.557 45.871,52.004 45.33,51.837
  region net PA11: 101.726,74.098 102.405,74.417 101.652,74.821 101.252,74.796
  region net PA12: 99.248,75.982 99.248,76.732 98.798,76.507 98.798,76.207
  region net +3V3: 99.716,82.037 100.091,82.037 101.138,82.317 100.597,82.484
  region net VBAT: 70.582,85.817 70.125,85.817 70.226,85.604 70.48,85.604
  region net VREF+: 68.601,81.245 69.059,81.245 68.957,81.032 68.703,81.032
  region net VDDA: 67.204,81.245 67.662,81.245 67.56,81.066 67.306,81.066
  region net VBAT: 68.944,63.742 69.401,63.742 69.299,63.955 69.045,63.955
  region net VREF+: 67.166,63.742 67.623,63.742 67.521,63.955 67.267,63.955
  region net VDDA: 65.388,63.742 65.845,63.742 65.743,63.955 65.489,63.955
  region net PA1: 64.681,81.374 65.079,81.148 64.889,81.011 64.66,81.141
  region net PA0: 66.016,81.132 65.692,81.455 65.613,81.232 65.793,81.053
  region net +3V3: 104.275,82.478 104.275,82.935 104.062,82.957 104.062,82.457
  region net +3V3: 42.322,51.998 42.322,52.456 42.535,52.477 42.535,51.977
  region net PB2: 71.395,80.76 71.853,80.76 71.751,80.973 71.497,80.973
  region net PB2: 46.91,120.074 46.586,119.751 46.809,119.671 46.989,119.851
  region net BOOT0: 74.524,87.71 74.201,87.387 74.122,87.61 74.301,87.789
  region net BOOT0: 59.308,121.588 58.985,121.264 59.208,121.185 59.387,121.365
  region net PA10: 91.293,74.019 91.75,74.019 91.649,74.232 91.395,74.232
  region net PA9: 92.387,72.748 91.93,72.749 92.032,72.962 92.286,72.962
  region net PA11: 81.641,53.191 82.098,53.191 82.02,53.404 81.72,53.404
  region net PA12: 82.53,53.191 82.987,53.191 82.909,53.404 82.609,53.404
  region net PA1: 67.182,42.032 68.136,41.077 67.303,41.02 67.123,41.2
  region net PA0: 64.589,41.301 64.589,42.651 63.959,42.103 63.959,41.849
  region net NRST: 49.958,47.072 48.608,47.071 49.133,47.702 49.433,47.702

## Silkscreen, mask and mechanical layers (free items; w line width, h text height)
Top Overlay:
  text "GND" at 46.736,123.825 h0.8
  text "GND" at 54.864,123.825 h0.8
  text "PA10" at 63.119,120.904 h0.8 r270
  text "PA9" at 65.786,120.904 h0.8 r270
  text "GND" at 68.453,120.904 h0.8 r270
  text "3V3" at 73.914,120.904 h0.8 r270
  text "SWDIO" at 76.454,120.904 h0.8 r270
  text "SWCLK" at 78.994,120.904 h0.8 r270
  text "GND" at 81.534,120.904 h0.8 r270
  text "BOOT1" at 45.537,120.381 h0.8
  text "BOOT0" at 54.808,120.381 h0.8
  text "3V3" at 46.736,117.983 h0.8
  text "3V3" at 54.82,117.994 h0.8
  text "GND" at 95.46,111.136 h0.8
  text "3V3" at 104.731,111.136 h0.8
  text "PE2" at 39.326,111.009 h0.8
  text "PE3" at 48.597,111.009 h0.8
  text "PE0" at 95.46,108.596 h0.8
  text "PE1" at 104.731,108.596 h0.8
  text "PE4" at 39.326,108.469 h0.8
  text "PE5" at 48.597,108.469 h0.8
  text "PB8" at 95.46,106.056 h0.8
  text "PB9" at 104.731,106.056 h0.8
  text "PE6" at 39.326,105.929 h0.8
  text "BAT" at 48.597,105.929 h0.8
  text "BOOT0" at 104.136,103.526 h0.8
  text "PB7" at 95.46,103.516 h0.8
  text "PC13" at 39.326,103.389 h0.8
  text "PC14" at 48.597,103.389 h0.8
  text "PB5" at 95.46,100.976 h0.8
  text "PB6" at 104.731,100.976 h0.8
  text "PC15" at 39.326,100.849 h0.8
  text "GND" at 48.597,100.849 h0.8
  text "PB3" at 95.46,98.436 h0.8
  text "PB4" at 104.731,98.436 h0.8
  text "3V3" at 39.326,98.309 h0.8
  text "OSCI" at 48.597,98.309 h0.8
  text "PD6" at 95.46,95.896 h0.8
  text "PD7" at 104.731,95.896 h0.8
  text "OSCO" at 39.326,95.769 h0.8
  text "NRST" at 48.597,95.769 h0.8
  text "PD4" at 95.46,93.356 h0.8
  text "PD5" at 104.731,93.356 h0.8
  text "PC0" at 39.326,93.229 h0.8
  text "PC1" at 48.597,93.229 h0.8
  text "PD2" at 95.46,90.816 h0.8
  text "PD3" at 104.731,90.816 h0.8
  text "PC2" at 39.326,90.689 h0.8
  text "PC3" at 48.597,90.689 h0.8
  text "PD0" at 95.46,88.276 h0.8
  text "PD1" at 104.731,88.276 h0.8
  text "GND" at 39.199,88.149 h0.8
  text "GND" at 48.597,88.149 h0.8
  text "PC11" at 95.46,85.736 h0.8
  text "PC12" at 104.731,85.736 h0.8
  text "VREF+" at 38.945,85.609 h0.8
  text "VDDA" at 48.343,85.609 h0.8
  text "PA15" at 95.46,83.196 h0.8
  text "PC10" at 104.731,83.196 h0.8
  text "PA0" at 39.326,83.069 h0.8
  text "PA1" at 48.597,83.069 h0.8
  text "3V3" at 95.46,80.656 h0.8
  text "PA14" at 104.731,80.656 h0.8
  text "PA2" at 39.326,80.529 h0.8
  text "PA3" at 48.597,80.529 h0.8
  text "NC" at 95.46,78.116 h0.8
  text "GND" at 104.731,78.116 h0.8
  text "GND" at 39.326,77.989 h0.8
  text "3V3" at 48.597,77.989 h0.8
  text "TH242B" at 82.042,75.946 h1.1 r270
  text "Ev Board" at 84.074,75.819 h1.1 r270
  text "LQFP100_V10" at 85.852,75.819 h1.1 r270
  text "MG32F157 series" at 87.757,75.819 h1.1 r270
  text "PA12" at 95.46,75.576 h0.8
  text "PA13" at 104.731,75.576 h0.8
  text "PA4" at 39.326,75.449 h0.8
  text "PA5" at 48.597,75.449 h0.8
  text "PA10" at 95.46,73.036 h0.8
  text "PA11" at 104.731,73.036 h0.8
  text "PA6" at 39.326,72.909 h0.8
  text "PA7" at 48.597,72.909 h0.8
  text "PA8" at 95.46,70.496 h0.8
  text "PA9" at 104.731,70.496 h0.8
  text "PC4" at 39.326,70.369 h0.8
  text "PC5" at 48.597,70.369 h0.8
  text "PC8" at 95.46,67.956 h0.8
  text "PC9" at 104.858,67.956 h0.8
  text "PB0" at 39.326,67.829 h0.8
  text "PB1" at 48.597,67.829 h0.8
  text "PC6" at 95.46,65.416 h0.8
  text "PC7" at 104.731,65.416 h0.8
  text "PB2" at 39.326,65.289 h0.8
  text "PE7" at 48.597,65.289 h0.8
  text "PD14" at 95.46,62.876 h0.8
  text "PD15" at 104.731,62.876 h0.8
  text "PE8" at 39.326,62.749 h0.8
  text "PE9" at 48.597,62.749 h0.8
  text "PE11" at 48.641,60.706 h0.8
  text "PD12" at 95.46,60.336 h0.8
  text "PD13" at 104.731,60.336 h0.8
  text "PE10" at 39.326,60.209 h0.8
  text "PD10" at 95.46,57.796 h0.8
  text "PD11" at 104.731,57.796 h0.8
  text "PE12" at 39.326,57.669 h0.8
  text "PE13" at 48.597,57.669 h0.8
  text "PD8" at 95.46,55.256 h0.8
  text "PD9" at 104.731,55.256 h0.8
  text "PE14" at 39.326,55.129 h0.8
  text "PE15" at 48.597,55.129 h0.8
  text "PB14" at 95.46,52.716 h0.8
  text "PB15" at 104.731,52.716 h0.8
  text "PB10" at 39.326,52.589 h0.8
  text "PB11" at 48.597,52.589 h0.8
  text "PB12" at 95.46,50.176 h0.8
  text "PB13" at 104.731,50.176 h0.8
  text "GND" at 39.326,50.049 h0.8
  text "3V3" at 48.47,50.049 h0.8
  text "PB13" at 99.396,44.842 h0.8
  text "PB14" at 99.396,42.302 h0.8
  text "PA0" at 62.484,39.751 h0.8
  text "PA1" at 72.136,39.751 h0.8
Top Solder:
  region: 67.814,99.608 65.909,101.64 65.909,101.767 66.925,102.783 68.957,100.751 67.814,99.608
